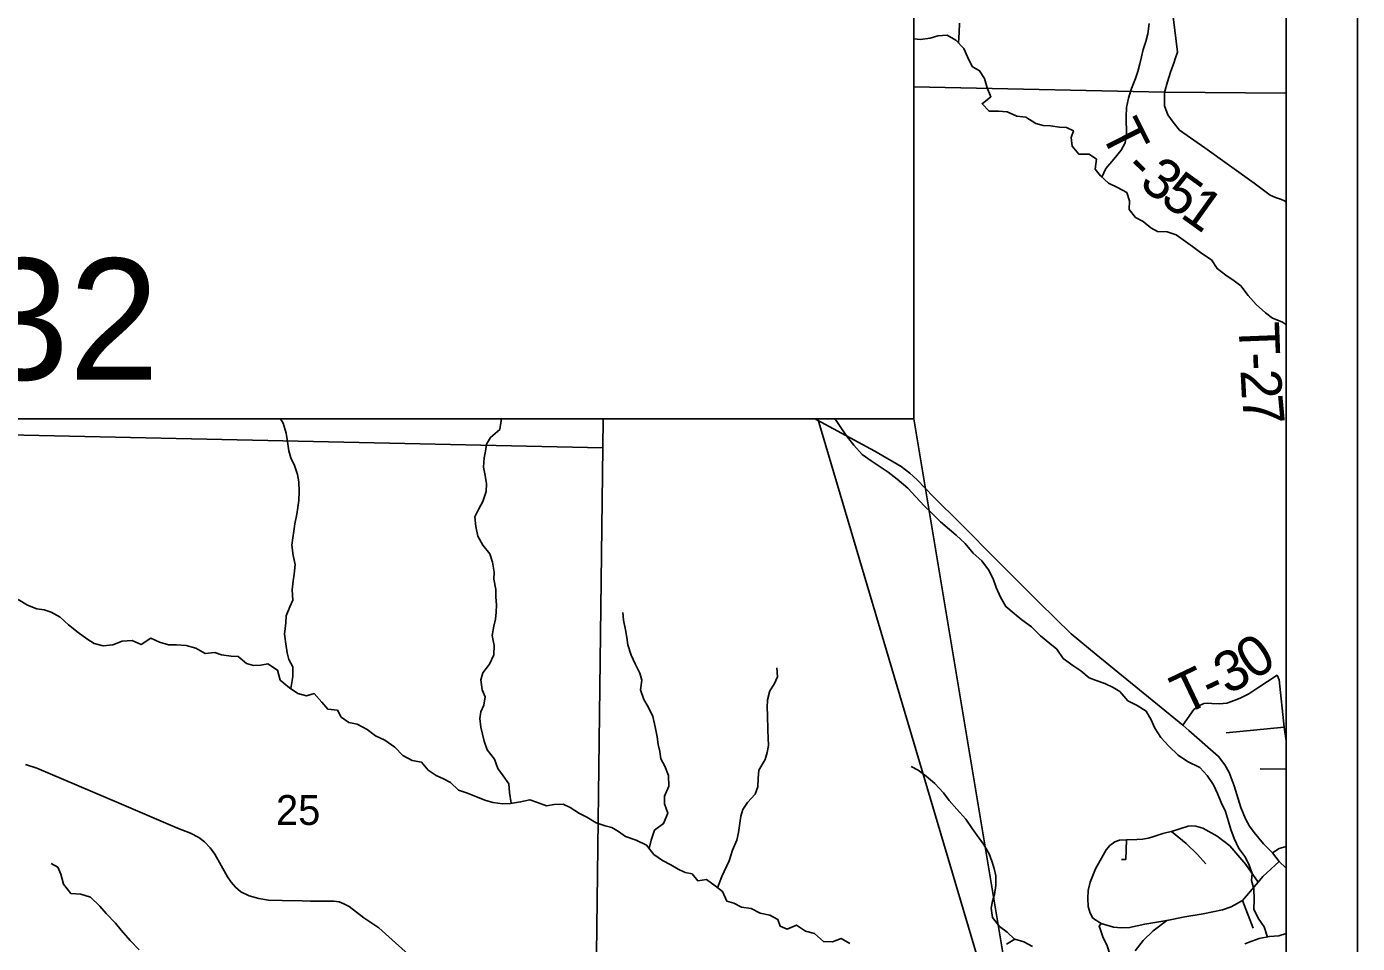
# Model space of a CAD drawing. Extents: x -20.5 to 34, y -66 to 23.9.
# Drawn here: x 7.132 to 9, y 17.643 to 18.93 of the extents above; entities that cross this region are included whole.
import ezdxf

# ---------------------------------------------------------------- set-up
doc = ezdxf.new("R2010")
doc.units = 0
for name, color, linetype in [('Default', 7, 'Continuous'), ('GM_X_County_Text', 7, 'Continuous'), ('GM_X_Minor_Lake', 7, 'Continuous'), ('GM_X_Minor_River_Text', 7, 'Continuous'), ('GM_X_Section_Text', 7, 'Continuous'), ('GM_X_State_Route', 7, 'Continuous'), ('GM_X_Township_Road', 7, 'Continuous'), ('GM_X_Township_Text', 7, 'Continuous'), ('SH_Cut_Line', 7, 'Continuous'), ('SH_Data', 7, 'Continuous'), ('SH_Text', 7, 'Continuous')]:
    doc.layers.add(name, color=color, linetype=linetype)

msp = doc.modelspace()

# ---------------------------------------------------------------- linework, layer by layer
at = {"layer": 'Default'}
msp.add_lwpolyline([(2.1, 20.9), (8.9, 20.9), (8.9, 14.1), (2.1, 14.1)], close=True, dxfattribs=at)
for points in [[(8.3774, 18.8452), (8.7292, 18.8379), (8.9, 18.8361), (8.9, 20.9), (2.1, 20.9), (2.1, 19.024), (2.1138, 19.0238), (2.8866, 19.0123), (2.9847, 19.0125), (3.3332, 19.0103), (5.1839, 18.9738), (5.2343, 18.9736), (5.2893, 18.9731), (5.9456, 18.969), (5.9451, 18.8918), (6.0429, 18.8899), (6.0928, 18.889), (6.2064, 18.8869)], [(8.0662, 14.9881), (8.0784, 15.8902), (8.0825, 16.3121), (8.087, 16.6605), (8.0955, 17.3258), (8.2289, 17.3235), (8.271, 17.3227), (8.5216, 17.3182), (8.9, 17.3115), (8.9, 18.8361), (8.7292, 18.8379), (8.3774, 18.8452)]]:
    msp.add_lwpolyline(points, dxfattribs=at)
at = {"layer": 'GM_X_County_Text'}
for p, q in [((8.8973, 17.9466), (8.8157, 17.9386)), ((8.9, 17.8875), (8.8637, 17.888)), ((8.8539, 17.6645), (8.8387, 17.7032))]:
    msp.add_line(p, q, dxfattribs=at)
for points in [[(8.7445, 18.8844), (8.7475, 18.8937), (8.7457, 18.9093), (8.741, 18.9471)], [(8.9, 18.6837), (8.8978, 18.6853), (8.8937, 18.6871), (8.8853, 18.6897), (8.8775, 18.6932), (8.855, 18.71), (8.7857, 18.7596), (8.7505, 18.7843), (8.7414, 18.7955), (8.7342, 18.8061), (8.7292, 18.8186), (8.7294, 18.8374), (8.7335, 18.852), (8.7378, 18.8656), (8.743, 18.8797), (8.7445, 18.8844)], [(8.755, 17.9492), (8.7704, 17.971), (8.7767, 17.976), (8.7844, 17.9798), (8.7899, 17.9803), (8.7958, 17.9798), (8.8064, 17.9792), (8.817, 17.9803), (8.8284, 17.9841), (8.8364, 17.9875), (8.8475, 17.9933), (8.8603, 18.0015), (8.8873, 18.0193)], [(8.9, 17.9271), (8.8973, 17.9466), (8.8902, 18.0127), (8.8873, 18.0193)], [(8.7328, 17.6753), (8.7015, 17.67), (8.6804, 17.6652), (8.6689, 17.6649), (8.6575, 17.6659), (8.6406, 17.671), (8.6288, 17.6784), (8.6251, 17.6853), (8.6222, 17.6945), (8.6216, 17.7058), (8.6221, 17.7171), (8.6252, 17.7289), (8.6326, 17.7478), (8.6476, 17.7744), (8.6526, 17.7803), (8.6598, 17.7855), (8.6661, 17.788), (8.6759, 17.7884), (8.6903, 17.7886), (8.6988, 17.7891), (8.7064, 17.7905), (8.7117, 17.792), (8.7269, 17.7973), (8.7328, 17.7987), (8.739, 17.8001), (8.7623, 17.8076), (8.7672, 17.808), (8.7731, 17.8076), (8.7829, 17.8045), (8.8032, 17.7935), (8.8211, 17.7801), (8.8324, 17.7667), (8.8434, 17.7539), (8.8607, 17.7287)], [(8.7871, 17.7546), (8.7756, 17.7675), (8.7599, 17.783), (8.739, 17.8001)], [(8.669, 17.7608), (8.675, 17.7608), (8.6759, 17.7884)], [(8.8807, 17.7701), (8.8902, 17.7762), (8.9, 17.779)], [(8.664, 17.6053), (8.6581, 17.616), (8.6526, 17.6277), (8.6487, 17.6393), (8.6426, 17.6523), (8.6394, 17.6621), (8.6374, 17.6671), (8.6406, 17.671)]]:
    msp.add_lwpolyline(points, dxfattribs=at)
at = {"layer": 'GM_X_Minor_Lake'}
msp.add_lwpolyline([(7.9415, 18.3792), (7.9409, 18.3387), (6.9356, 18.3607), (6.9358, 18.3792)], dxfattribs=at)
msp.add_lwpolyline([(7.9409, 18.3387), (7.9284, 17.3287), (7.0924, 17.3404), (6.9259, 17.3432), (6.9356, 18.3607)], close=True, dxfattribs=at)
at = {"layer": 'GM_X_Minor_River_Text'}
for points in [[(8.4404, 18.9066), (8.4411, 18.9219), (8.4416, 18.9348)], [(8.6414, 18.7182), (8.6468, 18.7304), (8.6583, 18.7435), (8.6687, 18.7565), (8.6743, 18.7665), (8.676, 18.7783), (8.6756, 18.8033), (8.6762, 18.8162), (8.679, 18.8295), (8.6829, 18.8428), (8.6884, 18.857), (8.692, 18.8669), (8.6945, 18.8775), (8.697, 18.8874), (8.6995, 18.8977), (8.7031, 18.9088), (8.706, 18.9198), (8.7077, 18.9339)], [(8.9, 18.5114), (8.8938, 18.5153), (8.8809, 18.5204), (8.8709, 18.5282), (8.8579, 18.5398), (8.8467, 18.5525), (8.8366, 18.566), (8.8271, 18.573), (8.8152, 18.5808), (8.8033, 18.5901), (8.7952, 18.6025), (8.7818, 18.6114), (8.7684, 18.6211), (8.7554, 18.6304), (8.7459, 18.6374), (8.7329, 18.6418), (8.7197, 18.642), (8.7101, 18.6472), (8.6994, 18.6561), (8.6887, 18.6616), (8.6795, 18.6729), (8.6804, 18.685), (8.6765, 18.6967), (8.6635, 18.7037), (8.6505, 18.71), (8.6394, 18.7201), (8.6321, 18.7298), (8.6338, 18.7435), (8.6234, 18.7509), (8.609, 18.7507), (8.5998, 18.7619), (8.5981, 18.7741), (8.6014, 18.7836), (8.5918, 18.788), (8.582, 18.7886), (8.5691, 18.7903), (8.5592, 18.7909), (8.5486, 18.7938), (8.5348, 18.8027), (8.522, 18.804), (8.5086, 18.8099), (8.4965, 18.8112), (8.4832, 18.811), (8.4732, 18.8215), (8.4856, 18.8312), (8.4805, 18.8436), (8.4765, 18.8568), (8.4699, 18.8677), (8.4592, 18.8736), (8.4529, 18.8872), (8.4478, 18.8989), (8.4363, 18.9109), (8.4245, 18.9175), (8.4113, 18.9166), (8.4003, 18.9134), (8.3867, 18.9116), (8.3774, 18.9128)], [(7.503, 18.0005), (7.5062, 18.0174), (7.506, 18.031), (7.5006, 18.0412), (7.4978, 18.051), (7.4961, 18.0635), (7.4943, 18.0771), (7.496, 18.0931), (7.4966, 18.1026), (7.5017, 18.1152), (7.5061, 18.1247), (7.5051, 18.1391), (7.5064, 18.1517), (7.5078, 18.1612), (7.5091, 18.1749), (7.5063, 18.1873), (7.5045, 18.2017), (7.5059, 18.212), (7.5076, 18.2215), (7.509, 18.2317), (7.5114, 18.2454), (7.5132, 18.2549), (7.5146, 18.2645), (7.5151, 18.277), (7.5145, 18.2906), (7.5125, 18.3012), (7.5085, 18.3137), (7.5034, 18.3246), (7.5002, 18.3344), (7.4985, 18.3473), (7.4968, 18.359), (7.4925, 18.373), (7.4888, 18.3792)], [(7.8122, 17.8396), (7.8099, 17.8547), (7.8093, 17.8668), (7.8012, 17.878), (7.7939, 17.8882), (7.7888, 17.9014), (7.7787, 17.9145), (7.7747, 17.927), (7.7699, 17.9466), (7.7686, 17.9584), (7.77, 17.9679), (7.774, 17.9774), (7.7757, 17.9892), (7.7718, 17.999), (7.7697, 18.013), (7.7725, 18.0229), (7.7818, 18.0348), (7.788, 18.0478), (7.7886, 18.0611), (7.7857, 18.0751), (7.7882, 18.088), (7.7903, 18.0979), (7.7913, 18.1078), (7.7919, 18.118), (7.791, 18.129), (7.7908, 18.1396), (7.7883, 18.1544), (7.7885, 18.1639), (7.7861, 18.1782), (7.7825, 18.1899), (7.7728, 18.2019), (7.7654, 18.2147), (7.763, 18.228), (7.7616, 18.2416), (7.7668, 18.2527), (7.7726, 18.263), (7.7774, 18.2771), (7.7779, 18.2881), (7.7759, 18.2995), (7.7734, 18.3112), (7.7747, 18.3245), (7.7765, 18.334), (7.7779, 18.3435), (7.7834, 18.3531), (7.7965, 18.3643), (7.7982, 18.3768), (7.7981, 18.3792)], [(8.8737, 17.6519), (8.8693, 17.6664), (8.8608, 17.6784), (8.8545, 17.6908), (8.8551, 17.7045), (8.8549, 17.7193), (8.8516, 17.731), (8.8523, 17.7409), (8.8483, 17.7526), (8.8424, 17.7646), (8.8336, 17.7763), (8.8269, 17.7902), (8.8222, 17.803), (8.819, 17.814), (8.815, 17.8279), (8.8087, 17.8407), (8.8036, 17.8532), (8.7981, 17.8656), (8.7892, 17.8788), (8.7788, 17.8896), (8.7617, 17.8981), (8.7483, 17.907), (8.7352, 17.9197), (8.7241, 17.932), (8.7156, 17.9448), (8.7105, 17.9565), (8.7038, 17.9689), (8.6909, 17.977), (8.6779, 17.9833), (8.6667, 17.9964), (8.6572, 18.0019), (8.6457, 18.0078), (8.6336, 18.0118), (8.6237, 18.0159), (8.6118, 18.0255), (8.6007, 18.033), (8.5869, 18.043), (8.578, 18.0558), (8.5684, 18.064), (8.5554, 18.0744), (8.5427, 18.0871), (8.5293, 18.0971), (8.5182, 18.1061), (8.5067, 18.1158), (8.499, 18.1289), (8.4931, 18.1425), (8.4887, 18.1546), (8.4825, 18.1674), (8.4728, 18.1797), (8.4606, 18.1906), (8.4494, 18.204), (8.4371, 18.216), (8.4275, 18.2238), (8.4149, 18.2346), (8.4026, 18.247), (8.3918, 18.257), (8.3803, 18.2698), (8.3691, 18.2821), (8.3542, 18.2944), (8.3415, 18.3045), (8.3289, 18.3126), (8.3174, 18.3204), (8.3048, 18.329), (8.2932, 18.3424), (8.2844, 18.3537), (8.2762, 18.3657), (8.2674, 18.3781), (8.2659, 18.3792)], [(7.5465, 17.9816), (7.5357, 17.9936), (7.5252, 17.9904), (7.513, 17.9936), (7.5012, 18.0018), (7.4881, 18.0126), (7.4845, 18.0265), (7.4711, 18.0351), (7.4609, 18.0334), (7.4507, 18.0332), (7.4409, 18.0358), (7.4294, 18.0454), (7.4195, 18.0461), (7.4059, 18.0481), (7.3963, 18.0514), (7.3828, 18.0497), (7.3698, 18.0571), (7.3561, 18.061), (7.3428, 18.062), (7.3315, 18.0622), (7.3189, 18.0658), (7.3067, 18.0713), (7.2929, 18.0627), (7.2803, 18.0682), (7.2663, 18.0673), (7.2535, 18.0621), (7.2396, 18.0604), (7.2274, 18.064), (7.2171, 18.0703), (7.2048, 18.0792), (7.191, 18.09), (7.1795, 18.1008), (7.1666, 18.1078), (7.157, 18.1111), (7.1468, 18.1125), (7.1335, 18.1176), (7.1205, 18.1254)], [(8.0059, 17.7762), (8.0088, 17.7878), (8.0135, 17.8019), (8.0263, 17.8112), (8.0321, 17.8257), (8.0277, 17.8389), (8.0276, 17.8496), (8.0338, 17.8637), (8.0332, 17.8785), (8.0281, 17.8917), (8.0226, 17.9018), (8.0209, 17.9121), (8.0185, 17.9219), (8.0172, 17.9329), (8.0147, 17.9469), (8.0111, 17.9616), (8.0048, 17.9752), (7.9986, 17.9853), (7.9939, 17.9989), (7.9959, 18.0122), (7.9928, 18.022), (7.9865, 18.0352), (7.9806, 18.0476), (7.9759, 18.062), (7.9746, 18.0722), (7.9729, 18.0832), (7.9701, 18.0964), (7.9691, 18.1074)], [(8.1022, 17.7209), (8.108, 17.7366), (8.1182, 17.7587), (8.1229, 17.7736), (8.1292, 17.7877), (8.1313, 17.7988), (8.133, 17.8086), (8.1347, 17.8216), (8.1376, 17.8311), (8.1442, 17.8407), (8.1547, 17.8526), (8.1587, 17.8629), (8.1589, 17.8743), (8.1598, 17.886), (8.1691, 17.901), (8.1719, 17.9109), (8.1737, 17.9208), (8.1731, 17.931), (8.1726, 17.942), (8.1723, 17.9636), (8.1717, 17.9735), (8.1723, 17.9849), (8.1755, 17.9974), (8.1814, 18.007), (8.1862, 18.0169), (8.1853, 18.0298)], [(8.2876, 17.6429), (8.2754, 17.6499), (8.2634, 17.6452), (8.2505, 17.6454), (8.2382, 17.6566), (8.2257, 17.6602), (8.2127, 17.6687), (8.1996, 17.6628), (8.19, 17.6669), (8.1865, 17.6767), (8.1754, 17.6826), (8.1617, 17.6854), (8.1492, 17.6917), (8.1355, 17.6937), (8.1248, 17.6993), (8.1149, 17.7022), (8.1091, 17.7157), (8.0987, 17.7235), (8.0865, 17.7325), (8.0744, 17.7308), (8.0663, 17.7405), (8.0564, 17.7426), (8.0469, 17.7471), (8.0366, 17.753), (8.0248, 17.7592), (8.0125, 17.7678), (8.0021, 17.7809), (7.988, 17.7879), (7.9728, 17.793), (7.9632, 17.8), (7.9537, 17.8056), (7.9442, 17.8081), (7.9316, 17.8121), (7.9187, 17.8199), (7.9084, 17.8254), (7.895, 17.8336), (7.8855, 17.8383), (7.8726, 17.8378), (7.862, 17.8361), (7.8495, 17.8405), (7.8388, 17.8445), (7.8256, 17.8416), (7.8113, 17.8395), (7.8007, 17.839), (7.7867, 17.8407), (7.7756, 17.8439), (7.7627, 17.849), (7.7497, 17.8545), (7.7387, 17.8581), (7.7272, 17.869), (7.7173, 17.8738), (7.707, 17.8785), (7.6959, 17.8863), (7.6867, 17.8972), (7.6734, 17.8997), (7.6604, 17.9067), (7.6489, 17.9183), (7.6351, 17.9283), (7.6221, 17.9345), (7.6103, 17.9431), (7.5965, 17.9508), (7.5844, 17.9529), (7.5737, 17.9607), (7.5686, 17.9705), (7.555, 17.9718), (7.5465, 17.9816)], [(8.5187, 17.6488), (8.5084, 17.6587), (8.4977, 17.6665), (8.488, 17.6793), (8.4859, 17.6925), (8.4881, 17.702), (8.4909, 17.7116), (8.4926, 17.7241), (8.4924, 17.7378), (8.4904, 17.748), (8.4872, 17.7585), (8.4833, 17.7687), (8.4751, 17.7823), (8.4662, 17.7946), (8.4596, 17.8044), (8.4504, 17.8172), (8.438, 17.8314), (8.4269, 17.8437), (8.4191, 17.8543), (8.4068, 17.8673), (8.3946, 17.8778), (8.3835, 17.8863), (8.3739, 17.8911)], [(7.2903, 17.6337), (7.2776, 17.6471), (7.2649, 17.6614), (7.2572, 17.6711), (7.2438, 17.6849), (7.2349, 17.6951), (7.2222, 17.7078), (7.2085, 17.7121), (7.1945, 17.713), (7.1841, 17.7261), (7.1805, 17.7401), (7.1762, 17.7499), (7.1666, 17.7551)], [(8.9, 17.657), (8.8899, 17.6535), (8.8767, 17.6525), (8.8623, 17.6496), (8.8518, 17.646), (8.842, 17.6425)], [(8.5439, 17.6388), (8.5317, 17.645), (8.5191, 17.649), (8.5075, 17.642)]]:
    msp.add_lwpolyline(points, dxfattribs=at)
at = {"layer": 'GM_X_State_Route'}
for points in [[(7.6824, 17.6149), (7.6265, 17.6649), (7.6055, 17.6789), (7.5851, 17.6948), (7.5777, 17.6986), (7.5709, 17.7012), (7.5636, 17.7022), (7.5309, 17.7023), (7.5191, 17.7028), (7.4909, 17.703), (7.4717, 17.7038), (7.4585, 17.706), (7.4447, 17.7098), (7.4329, 17.7155), (7.4255, 17.7217), (7.4196, 17.7287), (7.4143, 17.7364), (7.3966, 17.7682), (7.3899, 17.7771), (7.3821, 17.7854), (7.3742, 17.7915), (7.3626, 17.7976), (7.344, 17.8049), (7.2623, 17.8396), (7.1468, 17.8888), (7.1309, 17.8941)], [(8.8904, 17.7577), (8.8674, 17.737), (8.8607, 17.7287), (8.8387, 17.7032), (8.823, 17.6941), (8.8109, 17.69), (8.7834, 17.6844), (8.7579, 17.6802), (8.7328, 17.6753), (8.7133, 17.6607), (8.6994, 17.6472), (8.6882, 17.6326)]]:
    msp.add_lwpolyline(points, dxfattribs=at)
at = {"layer": 'GM_X_Township_Road'}
msp.add_lwpolyline([(8.9, 17.7485), (8.8904, 17.7577), (8.8807, 17.7701), (8.8684, 17.7827), (8.8552, 17.7985), (8.8485, 17.8076), (8.8428, 17.818), (8.8362, 17.8337), (8.8272, 17.8642), (8.8202, 17.883), (8.8139, 17.8937), (8.8051, 17.9053), (8.7635, 17.9418), (8.755, 17.9492), (8.6336, 18.0484), (8.5982, 18.0776), (8.5536, 18.1214), (8.495, 18.1798), (8.443, 18.2322), (8.4051, 18.2699), (8.3816, 18.2941), (8.3717, 18.303), (8.3595, 18.3122), (8.3227, 18.334), (8.2415, 18.3777), (8.2389, 18.3792)], dxfattribs=at)
at = {"layer": 'SH_Cut_Line'}
msp.add_lwpolyline([(8.0662, 14.9881), (8.0784, 15.8902), (8.0825, 16.3121), (8.087, 16.6605), (8.0955, 17.3258), (8.2289, 17.3235), (8.271, 17.3227), (8.5216, 17.3182), (8.9, 17.3115), (8.9, 20.9), (2.1, 20.9), (2.1, 14.4131)], dxfattribs=at)
at = {"layer": 'SH_Data'}
for p, q in [((9, 21), (9, 14)), ((8.9, 20.9), (8.9, 14.1))]:
    msp.add_line(p, q, dxfattribs=at)
at = {"layer": 'SH_Text'}
for points in [[(6.2064, 19.1628), (8.3774, 19.1628), (8.3774, 18.3792), (6.2064, 18.3792)], [(8.5505, 17.3404), (8.3774, 18.3792), (8.2428, 18.3792)]]:
    msp.add_lwpolyline(points, close=True, dxfattribs=at)

# ---------------------------------------------------------------- texts
at = {"layer": 'GM_X_Section_Text'}
for s, rotation, p in [('T', 296.7903, (8.6385, 18.7819)), ('-', 315.7119, (8.6697, 18.7275)), ('3', 322.4037, (8.6919, 18.7065)), ('5', 324.2363, (8.7212, 18.684)), ('1', 324.3638, (8.7497, 18.6634)), ('T', 272.2077, (8.8332, 18.5143)), ('-', 272.3654, (8.8349, 18.4716)), ('2', 273.0013, (8.8359, 18.4476)), ('7', 275.498, (8.8379, 18.41)), ('0', 33.7153, (8.8543, 18.011)), ('3', 27.2211, (8.8174, 17.9915)), ('T', 25.4984, (8.7565, 17.9625)), ('-', 25.4366, (8.7948, 17.9807))]:
    msp.add_text(s, height=0.0568, rotation=rotation, dxfattribs=at).set_placement(p)
at = {"layer": 'GM_X_Township_Text'}
msp.add_text('25', height=0.04186, rotation=0, dxfattribs=at).set_placement((7.4823, 17.8092))
at = {"layer": 'SH_Text'}
msp.add_text('SLM 17.32', height=0.17, dxfattribs=at).set_placement((6.2187, 18.4342))

doc.saveas('drawing.dxf')
